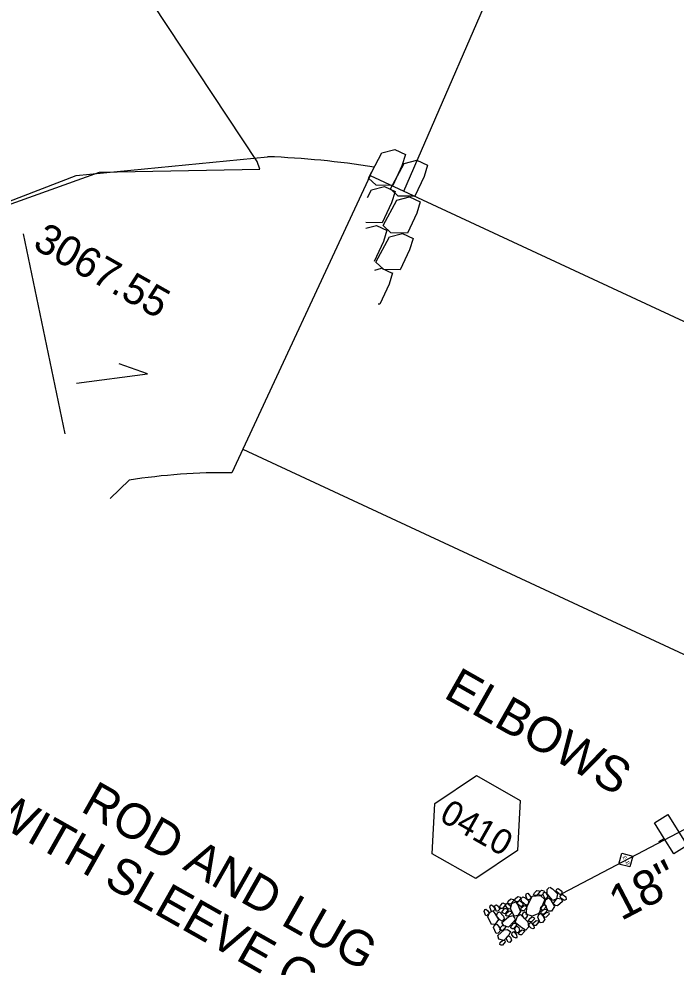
# Model space of a CAD drawing. Extents: x 1116825 to 1117461, y 843538 to 843929.
# Drawn here: x 1116903.7 to 1116969.1, y 843703.9 to 843798.2 of the extents above; entities that cross this region are included whole.
import ezdxf

# ---------------------------------------------------------------- set-up
doc = ezdxf.new("R2010")
doc.units = 0
for name, color, linetype in [('Exist Plan Preparation Watershed Red', 7, 'Continuous'), ('Prop Approach Slab', 7, 'Continuous'), ('Prop Drainage Structure Box Number Symbol CELL', 7, 'Continuous'), ('Prop Drainage Structure Bridge', 7, 'Continuous'), ('Prop Drainage Structure Pipe Alternate 18in Label', 7, 'Continuous'), ('Prop Drainage Structure Pipe CSP Rod and Lug with Sleeve Gaskets CELL', 7, 'Continuous'), ('Prop Drainage Structure Pipe CSP Rod and Lug with Sleeve Gaskets Label', 7, 'Continuous'), ('Prop Drainage Structure Pipe Elbow Alternate CELL', 7, 'Continuous'), ('Prop Drainage Structure Pipe Elbow Alternate Label', 7, 'Continuous'), ('Prop Drainage Structure Pipe RCP 18in Class IV', 7, 'Continuous'), ('Prop Erosion Rip Rap Pad at Outlet CELL', 7, 'Continuous'), ('Prop Erosion Rip Rap Single Stone CELL', 7, 'Continuous'), ('Prop Plan Preparation Crest', 7, 'Continuous'), ('Prop SS Transition Line', 7, 'Continuous')]:
    doc.layers.add(name, color=color, linetype=linetype)

msp = doc.modelspace()

# ---------------------------------------------------------------- linework, layer by layer
at = {"layer": 'Exist Plan Preparation Watershed Red'}
msp.add_lwpolyline([(1116927.444, 843784.028), (1116891.673, 843838.048), (1116872.452, 843885.499), (1116883.337, 843929.283), (1116848.462, 843867.67), (1116833.693, 843822.48), (1116824.752, 843793.043), (1116825.609, 843759.089), (1116828.621, 843758.516), (1116846.986, 843760.418), (1116862.566, 843764.185), (1116875.956, 843768.327), (1116885.93, 843773.73), (1116911.76, 843782.964), (1116927.705, 843783.267)], close=True, dxfattribs=at)
at = {"layer": 'Prop Approach Slab'}
for centre, radius, start, end in [((1116925.123, 843694.626), 89.938, 81.086, 87.86188), ((1116924.154, 843692.54), 60.546, 89.26755, 98.98543)]:
    msp.add_arc(centre, radius, start, end, dxfattribs=at)
at = {"layer": 'Prop Drainage Structure Box Number Symbol CELL'}
msp.add_lwpolyline([(1116949.242, 843722.974), (1116953.594, 843720.511), (1116953.337, 843715.517), (1116949.188, 843712.727), (1116944.836, 843715.19), (1116945.094, 843720.183), (1116949.242, 843722.974)], dxfattribs=at)
at = {"layer": 'Prop Drainage Structure Bridge'}
for p, q in [((1116938.666, 843782.63), (1116939.059, 843783.477)), ((1116938.666, 843782.63), (1116924.928, 843753.081)), ((1116938.666, 843782.63), (1116984.005, 843761.551)), ((1116926.018, 843755.427), (1116971.357, 843734.347))]:
    msp.add_line(p, q, dxfattribs=at)
at = {"layer": 'Prop Drainage Structure Pipe CSP Rod and Lug with Sleeve Gaskets CELL'}
msp.add_line((1116967.911, 843716.732), (1116967.911, 843716.732), dxfattribs=at)
msp.add_line((1116967.911, 843716.732), (1116967.911, 843716.732), dxfattribs=at)
msp.add_lwpolyline([(1116967.387, 843716.405), (1116967.911, 843716.732), (1116966.95, 843718.271), (1116968.292, 843719.109), (1116970.214, 843716.03), (1116968.872, 843715.192), (1116967.911, 843716.732)], dxfattribs=at)
at = {"layer": 'Prop Drainage Structure Pipe Elbow Alternate CELL'}
msp.add_line((1116964.103, 843714.571), (1116964.103, 843714.571), dxfattribs=at)
msp.add_line((1116964.103, 843714.571), (1116964.103, 843714.571), dxfattribs=at)
msp.add_lwpolyline([(1116963.712, 843715.254), (1116964.787, 843714.962), (1116964.495, 843713.888), (1116963.42, 843714.179), (1116963.712, 843715.254)], dxfattribs=at)
at = {"layer": 'Prop Drainage Structure Pipe RCP 18in Class IV'}
msp.add_line((1116978.978, 843722.357), (1116957.744, 843711.232), dxfattribs=at)
at = {"layer": 'Prop Erosion Rip Rap Pad at Outlet CELL'}
msp.add_line((1116957.744, 843711.232), (1116957.744, 843711.232), dxfattribs=at)
msp.add_line((1116957.744, 843711.232), (1116957.744, 843711.232), dxfattribs=at)
for points in [[(1116954.352, 843711.287), (1116954.504, 843711.129), (1116954.694, 843710.844), (1116954.522, 843710.664), (1116954.339, 843710.617), (1116954.17, 843711.032), (1116954.228, 843711.241), (1116954.352, 843711.287)], [(1116954.931, 843711.127), (1116955.005, 843711.324), (1116955.266, 843711.561), (1116955.467, 843711.518), (1116955.54, 843711.378), (1116955.218, 843711.051), (1116955.062, 843711.047), (1116954.931, 843711.127)], [(1116955.436, 843711.145), (1116955.47, 843711.342), (1116955.732, 843711.578), (1116955.944, 843711.512), (1116956.006, 843711.396), (1116955.715, 843711.065), (1116955.543, 843711.054), (1116955.436, 843711.145)], [(1116956.112, 843711.383), (1116956.193, 843711.248), (1116956.347, 843710.973), (1116956.202, 843710.798), (1116956.086, 843710.736), (1116955.883, 843711.104), (1116955.916, 843711.359), (1116956.112, 843711.383)], [(1116956.555, 843711.893), (1116956.801, 843711.707), (1116957.321, 843711.209), (1116957.202, 843710.721), (1116956.857, 843710.569), (1116956.276, 843711.202), (1116956.266, 843711.652), (1116956.477, 843711.852)], [(1116957.557, 843711.136), (1116957.441, 843711.243), (1116957.135, 843711.467), (1116957.248, 843711.685), (1116957.364, 843711.746), (1116957.738, 843711.468), (1116957.743, 843711.234), (1116957.557, 843711.136)], [(1116957.98, 843710.558), (1116957.853, 843710.668), (1116957.534, 843710.916), (1116957.671, 843711.107), (1116957.783, 843711.176), (1116958.122, 843710.909), (1116958.162, 843710.663), (1116957.98, 843710.558)], [(1116951.53, 843709.849), (1116951.627, 843710.058), (1116951.88, 843710.31), (1116952.069, 843710.232), (1116952.126, 843710.124), (1116951.836, 843709.773), (1116951.66, 843709.769), (1116951.53, 843709.849)], [(1116952.485, 843709.65), (1116952.369, 843709.757), (1116952.14, 843710.022), (1116952.199, 843710.231), (1116952.287, 843710.288), (1116952.593, 843710.063), (1116952.622, 843709.841), (1116952.542, 843709.71)], [(1116952.381, 843710.298), (1116952.416, 843710.494), (1116952.677, 843710.73), (1116952.89, 843710.665), (1116952.951, 843710.548), (1116952.665, 843710.21), (1116952.489, 843710.206), (1116952.381, 843710.298)], [(1116953.115, 843710.407), (1116953.356, 843710.119), (1116953.639, 843709.467), (1116953.37, 843709.078), (1116952.992, 843709.007), (1116952.647, 843709.775), (1116952.773, 843710.267), (1116953.115, 843710.407)], [(1116953.077, 843710.516), (1116953.112, 843710.712), (1116953.373, 843710.949), (1116953.586, 843710.883), (1116953.647, 843710.767), (1116953.361, 843710.428), (1116953.185, 843710.424), (1116953.077, 843710.516)], [(1116953.708, 843709.938), (1116953.569, 843710.033), (1116953.278, 843710.266), (1116953.414, 843710.496), (1116953.515, 843710.549), (1116953.858, 843710.255), (1116953.857, 843710.106), (1116953.708, 843709.938)], [(1116953.859, 843710.928), (1116954.092, 843710.823), (1116954.444, 843710.475), (1116954.368, 843710.168), (1116954.182, 843710.07), (1116953.716, 843710.467), (1116953.706, 843710.768), (1116953.859, 843710.928)], [(1116954.21, 843709.303), (1116954.272, 843709.899), (1116954.789, 843711.002), (1116955.633, 843711.052), (1116956.045, 843710.646), (1116955.44, 843709.259), (1116954.804, 843709.003), (1116954.17, 843709.193)], [(1116956.421, 843710.834), (1116956.657, 843710.572), (1116957.003, 843709.954), (1116956.703, 843709.509), (1116956.387, 843709.49), (1116956.014, 843710.273), (1116956.135, 843710.663), (1116956.421, 843710.834)], [(1116956.88, 843710.225), (1116957.004, 843710.439), (1116957.291, 843710.778), (1116957.664, 843710.707), (1116957.802, 843710.464), (1116957.314, 843710.039), (1116957.067, 843710.057), (1116956.88, 843710.225)], [(1116950.19, 843709.707), (1116950.342, 843709.55), (1116950.532, 843709.264), (1116950.36, 843709.084), (1116950.177, 843709.037), (1116950.008, 843709.453), (1116950.066, 843709.661), (1116950.19, 843709.707)], [(1116950.863, 843709.537), (1116951.084, 843709.248), (1116951.433, 843708.661), (1116951.118, 843708.208), (1116950.747, 843708.181), (1116950.386, 843708.94), (1116950.542, 843709.358), (1116950.863, 843709.537)], [(1116950.756, 843710.134), (1116950.908, 843709.977), (1116951.098, 843709.691), (1116950.926, 843709.511), (1116950.743, 843709.464), (1116950.574, 843709.879), (1116950.632, 843710.088), (1116950.756, 843710.134)], [(1116951.238, 843710.14), (1116951.397, 843709.987), (1116951.587, 843709.701), (1116951.415, 843709.522), (1116951.232, 843709.475), (1116951.063, 843709.89), (1116951.121, 843710.099), (1116951.238, 843710.14)], [(1116951.797, 843708.496), (1116951.571, 843708.644), (1116951.253, 843709.041), (1116951.341, 843709.324), (1116951.527, 843709.422), (1116951.939, 843708.997), (1116952, 843708.732), (1116951.797, 843708.496)], [(1116951.747, 843709.399), (1116951.838, 843709.507), (1116952.071, 843709.798), (1116952.316, 843709.69), (1116952.377, 843709.573), (1116952.06, 843709.218), (1116951.89, 843709.297), (1116951.747, 843709.399)], [(1116952.176, 843709.072), (1116952.23, 843709.288), (1116952.496, 843709.517), (1116952.708, 843709.451), (1116952.754, 843709.327), (1116952.471, 843709.02), (1116952.307, 843708.993), (1116952.176, 843709.072)], [(1116953.671, 843709.632), (1116953.698, 843709.825), (1116953.98, 843710.042), (1116954.176, 843710.007), (1116954.249, 843709.868), (1116953.955, 843709.544), (1116953.779, 843709.541), (1116953.671, 843709.632)], [(1116954.036, 843709.429), (1116954.211, 843709.284), (1116954.284, 843708.996), (1116954.14, 843708.762), (1116953.987, 843708.77), (1116953.783, 843709.138), (1116953.919, 843709.367), (1116954.036, 843709.429)], [(1116955.644, 843709.248), (1116955.852, 843709.041), (1116956.056, 843708.673), (1116955.816, 843708.359), (1116955.573, 843708.35), (1116955.338, 843708.908), (1116955.466, 843709.154), (1116955.644, 843709.248)], [(1116955.631, 843709.686), (1116955.666, 843709.882), (1116955.931, 843710.111), (1116956.143, 843710.064), (1116956.181, 843709.936), (1116955.902, 843709.621), (1116955.762, 843709.606), (1116955.631, 843709.686)], [(1116955.652, 843709.271), (1116955.717, 843709.484), (1116955.987, 843709.685), (1116956.191, 843709.655), (1116956.265, 843709.515), (1116955.935, 843709.183), (1116955.782, 843709.192), (1116955.652, 843709.271)], [(1116955.924, 843708.96), (1116955.955, 843709.164), (1116956.22, 843709.393), (1116956.437, 843709.339), (1116956.475, 843709.21), (1116956.192, 843708.903), (1116956.055, 843708.881), (1116955.924, 843708.96)], [(1116953.128, 843708.693), (1116952.941, 843708.446), (1116952.42, 843707.915), (1116951.963, 843708.05), (1116951.784, 843708.371), (1116952.426, 843708.936), (1116952.85, 843709.051), (1116953.068, 843708.75)], [(1116952.661, 843707.834), (1116952.7, 843708.003), (1116952.976, 843708.287), (1116953.188, 843708.221), (1116953.226, 843708.092), (1116952.94, 843707.754), (1116952.804, 843707.731), (1116952.661, 843707.834)], [(1116954.078, 843707.641), (1116953.756, 843707.838), (1116953.107, 843708.356), (1116953.329, 843708.987), (1116953.627, 843709.154), (1116954.366, 843708.426), (1116954.428, 843707.895), (1116954.126, 843707.567)], [(1116954.435, 843708.521), (1116954.485, 843708.706), (1116954.751, 843708.915), (1116954.959, 843708.877), (1116955.033, 843708.737), (1116954.718, 843708.433), (1116954.565, 843708.442), (1116954.435, 843708.521)], [(1116954.866, 843707.74), (1116954.689, 843707.795), (1116954.477, 843708.009), (1116954.495, 843708.256), (1116954.692, 843708.37), (1116954.942, 843708.027), (1116954.978, 843707.809), (1116954.866, 843707.74)], [(1116954.869, 843708.147), (1116954.912, 843708.347), (1116955.177, 843708.576), (1116955.382, 843708.526), (1116955.42, 843708.397), (1116955.148, 843708.086), (1116955.008, 843708.072), (1116954.869, 843708.147)], [(1116951.279, 843708.204), (1116951.444, 843708.004), (1116951.659, 843707.613), (1116951.404, 843707.31), (1116951.201, 843707.263), (1116950.949, 843707.872), (1116951.058, 843708.117), (1116951.279, 843708.204)], [(1116952.611, 843707.422), (1116952.465, 843707.098), (1116951.967, 843706.578), (1116951.479, 843706.697), (1116951.378, 843707.059), (1116952.003, 843707.655), (1116952.343, 843707.686), (1116952.657, 843707.446)], [(1116951.584, 843707.662), (1116951.627, 843707.863), (1116951.884, 843708.107), (1116952.096, 843708.041), (1116952.158, 843707.925), (1116951.863, 843707.582), (1116951.692, 843707.57), (1116951.584, 843707.662)], [(1116953.191, 843706.808), (1116952.966, 843706.897), (1116952.769, 843707.139), (1116952.788, 843707.367), (1116952.97, 843707.472), (1116953.22, 843707.129), (1116953.279, 843706.923), (1116953.191, 843706.808)], [(1116953.295, 843708), (1116953.47, 843707.855), (1116953.543, 843707.567), (1116953.399, 843707.333), (1116953.246, 843707.341), (1116953.043, 843707.709), (1116953.179, 843707.939), (1116953.295, 843708)], [(1116953.468, 843707.201), (1116953.499, 843707.405), (1116953.765, 843707.634), (1116953.977, 843707.588), (1116954.015, 843707.459), (1116953.744, 843707.148), (1116953.607, 843707.126), (1116953.468, 843707.201)], [(1116951.56, 843706.186), (1116951.591, 843706.39), (1116951.857, 843706.619), (1116952.073, 843706.565), (1116952.111, 843706.437), (1116951.84, 843706.125), (1116951.699, 843706.111), (1116951.56, 843706.186)], [(1116952.477, 843707.055), (1116952.645, 843706.906), (1116952.718, 843706.618), (1116952.57, 843706.391), (1116952.417, 843706.4), (1116952.214, 843706.767), (1116952.361, 843706.994), (1116952.477, 843707.055)]]:
    msp.add_lwpolyline(points, dxfattribs=at)
at = {"layer": 'Prop Erosion Rip Rap Single Stone CELL'}
for points in [[(1116951.156, 843807.128), (1116952.78, 843805.86), (1116942.003, 843781.038)], [(1116942.181, 843784.738), (1116941.833, 843783.604), (1116940.916, 843781.632), (1116939.26, 843781.658), (1116938.496, 843782.385), (1116939.844, 843784.901), (1116941.116, 843785.234), (1116942.181, 843784.738)], [(1116944.392, 843783.67), (1116944.044, 843782.536), (1116943.127, 843780.564), (1116941.471, 843780.59), (1116940.707, 843781.317), (1116942.055, 843783.833), (1116943.327, 843784.166), (1116944.392, 843783.67)], [(1116941.15, 843781.047), (1116940.802, 843779.913), (1116939.885, 843777.94), (1116938.229, 843777.966)], [(1116938.41, 843780.452), (1116938.815, 843781.208), (1116940.086, 843781.54), (1116941.152, 843781.045)], [(1116943.658, 843780.009), (1116943.31, 843778.875), (1116942.393, 843776.903), (1116940.737, 843776.929), (1116939.973, 843777.656), (1116941.322, 843780.172), (1116942.593, 843780.505), (1116943.658, 843780.009)], [(1116938.259, 843777.398), (1116939.308, 843777.673), (1116940.373, 843777.177)], [(1116940.333, 843777.198), (1116939.985, 843776.064), (1116939.068, 843774.092)], [(1116942.94, 843776.371), (1116942.592, 843775.237), (1116941.675, 843773.265), (1116940.019, 843773.291), (1116939.255, 843774.018), (1116940.604, 843776.534), (1116941.875, 843776.867), (1116942.94, 843776.371)], [(1116939.124, 843773.234), (1116939.802, 843773.411), (1116940.867, 843772.916)], [(1116940.902, 843772.961), (1116940.554, 843771.828), (1116939.637, 843769.855), (1116939.462, 843769.858)]]:
    msp.add_lwpolyline(points, dxfattribs=at)
at = {"layer": 'Prop Plan Preparation Crest'}
msp.add_line((1116904.15, 843776.836), (1116908.305, 843756.945), dxfattribs=at)
msp.add_lwpolyline([(1116909.464, 843762.001), (1116916.511, 843762.912), (1116913.718, 843763.916)], dxfattribs=at)
at = {"layer": 'Prop SS Transition Line'}
msp.add_line((1116912.817, 843750.527), (1116914.697, 843752.343), dxfattribs=at)
msp.add_lwpolyline([(1116893.696, 843776.58), (1116909.438, 843782.639), (1116928.479, 843784.5)], dxfattribs=at)

# ---------------------------------------------------------------- texts
at = {"layer": 'Prop Drainage Structure Box Number Symbol CELL'}
msp.add_text('0410', height=2.5, rotation=330.48854, dxfattribs=at).set_placement((1116945.433, 843718.555))
at = {"layer": 'Prop Drainage Structure Pipe Alternate 18in Label'}
msp.add_text('18"', height=3.5, rotation=27.64988, dxfattribs=at).set_placement((1116963.634, 843708.489))
at = {"layer": 'Prop Drainage Structure Pipe CSP Rod and Lug with Sleeve Gaskets Label'}
for s, p in [('WITH SLEEVE GASKETS', (1116900.516, 843718.69)), ('ROD AND LUG ', (1116909.756, 843719.492))]:
    msp.add_text(s, height=3.5, rotation=330.48854, dxfattribs=at).set_placement(p)
at = {"layer": 'Prop Drainage Structure Pipe Elbow Alternate CELL'}
msp.add_text('ELB', height=0.36, rotation=299.81344, dxfattribs=at).set_placement((1116963.762, 843714.865))
at = {"layer": 'Prop Drainage Structure Pipe Elbow Alternate Label'}
msp.add_text('ELBOWS', height=3.5, rotation=330.48854, dxfattribs=at).set_placement((1116945.866, 843730.788))
at = {"layer": 'Prop Plan Preparation Crest'}
msp.add_text('3067.55', height=3, rotation=330.48854, dxfattribs=at).set_placement((1116904.988, 843775.474))

doc.saveas('drawing.dxf')
